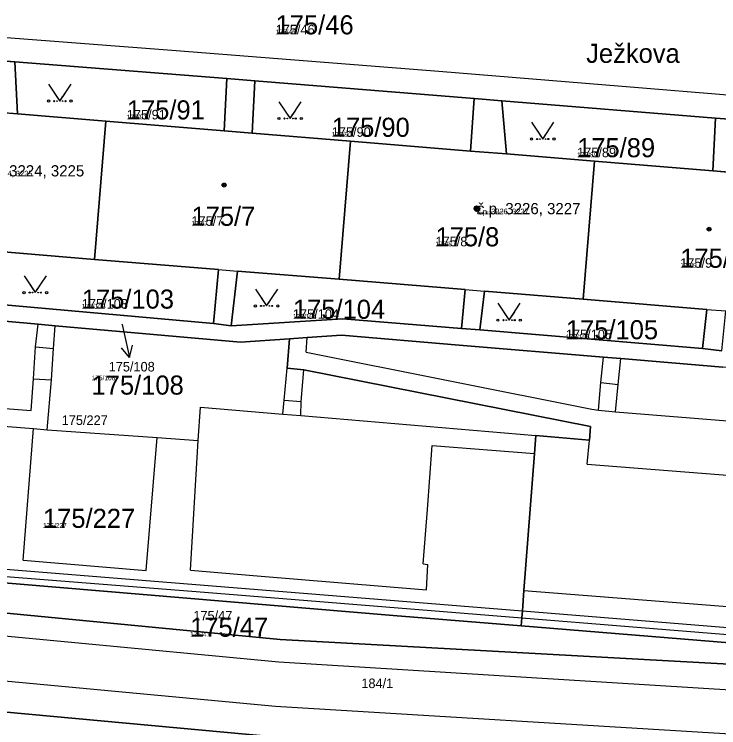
# Model space of a CAD drawing. Extents: x -759873 to -758487, y -975024 to -973516.
# Drawn here: x -759605.8 to -759543, y -974770.4 to -974706.8 of the extents above; entities that cross this region are included whole.
import ezdxf

# ---------------------------------------------------------------- set-up
doc = ezdxf.new("R2010")
doc.units = 0
for name, color, linetype in [('KAT_02_hranice parcel', 7, 'Continuous'), ('KAT_03_1000_st čísla parcelní', 7, 'Continuous'), ('KAT_03_1000_čísla parcelní', 7, 'Continuous'), ('KAT_03_1000_čísla popisná', 7, 'Continuous'), ('KAT_03_250_st čísla parcelní', 7, 'Continuous'), ('KAT_03_250_čísla parcelní', 7, 'Continuous'), ('KAT_03_250_čísla popisná', 7, 'Continuous'), ('KAT_03_500_st čísla parcelní', 7, 'Continuous'), ('KAT_03_500_čísla parcelní', 7, 'Continuous'), ('KAT_03_500_čísla popisná', 7, 'Continuous'), ('KAT_04_vnitřní kresba', 7, 'Continuous'), ('KAT_05_1000_značky kultur', 7, 'Continuous'), ('KAT_05_250_značky kultur', 7, 'Continuous'), ('KAT_05_500_značky kultur', 7, 'Continuous'), ('KAT_07_1000_značky budov', 7, 'Continuous'), ('KAT_07_250_značky budov', 7, 'Continuous'), ('KAT_07_500_značky budov', 7, 'Continuous'), ('KAT_12_pomocná šipka', 7, 'Continuous'), ('KAT_13_popis', 7, 'Continuous'), ('KAT_14_plocha_budovy', 7, 'Continuous'), ('KAT_14_plocha_pozemek', 7, 'Continuous')]:
    doc.layers.add(name, color=color, linetype=linetype)

msp = doc.modelspace()

# ---------------------------------------------------------------- linework, layer by layer
at = {"layer": 'KAT_02_hranice parcel'}
for p, q in [((-759605.74, -974711.03), (-759608.29, -974710.84)), ((-759605.74, -974711.03), (-759586.84, -974712.52)), ((-759584.35, -974712.72), (-759586.84, -974712.52)), ((-759584.35, -974712.72), (-759564.79, -974714.3)), ((-759562.33, -974714.49), (-759564.79, -974714.3)), ((-759562.33, -974714.49), (-759543.3, -974716.04)), ((-759540.86, -974716.24), (-759543.3, -974716.04)), ((-759598.63, -974728.63), (-759597.63, -974716.32)), ((-759576.84, -974730.41), (-759575.83, -974718.1)), ((-759555.1, -974732.19), (-759554.09, -974719.88)), ((-759607.69, -974732.58), (-759588.03, -974734.34)), ((-759588.03, -974734.34), (-759586.45, -974734.54)), ((-759565.94, -974734.78), (-759564.29, -974734.9)), ((-759564.29, -974734.9), (-759544.46, -974736.56)), ((-759544.46, -974736.56), (-759542.72, -974736.79))]:
    msp.add_line(p, q, dxfattribs=at)
for points in [[(-759597.63, -974716.32), (-759605.49, -974715.67), (-759605.74, -974711.03)], [(-759586.84, -974712.52), (-759587.06, -974717.18), (-759597.63, -974716.32)], [(-759575.83, -974718.1), (-759584.58, -974717.38), (-759584.35, -974712.72)], [(-759564.79, -974714.3), (-759565.13, -974718.98), (-759575.83, -974718.1)], [(-759554.09, -974719.88), (-759561.93, -974719.24), (-759562.33, -974714.49)], [(-759543.3, -974716.04), (-759543.55, -974720.74), (-759554.09, -974719.88)], [(-759607.69, -974732.58), (-759607.44, -974727.9), (-759598.63, -974728.63)], [(-759598.63, -974728.63), (-759587.58, -974729.53), (-759588.03, -974734.34)], [(-759586.45, -974734.54), (-759585.9, -974729.67), (-759576.84, -974730.41)], [(-759576.84, -974730.41), (-759565.6, -974731.33), (-759565.94, -974734.78)], [(-759647.22, -974730.88), (-759631.63, -974732.18), (-759609.62, -974733.88), (-759603.65, -974734.41), (-759602.12, -974734.54), (-759585.63, -974736), (-759581.26, -974735.71)], [(-759564.29, -974734.9), (-759563.89, -974731.47), (-759555.1, -974732.19)], [(-759555.1, -974732.19), (-759544.08, -974733.09), (-759544.46, -974736.56)], [(-759586.45, -974734.54), (-759576.49, -974733.94), (-759565.94, -974734.78)], [(-759560.6, -974761.29), (-759560.55, -974760.58), (-759560.5, -974759.95), (-759560.36, -974758.15), (-759559.43, -974745.94), (-759559.31, -974744.32), (-759554.53, -974744.73), (-759554.44, -974743.54), (-759579.98, -974738.48), (-759581.47, -974738.34), (-759581.26, -974735.71)], [(-759581.26, -974735.71), (-759579.69, -974735.6), (-759576.63, -974735.4), (-759566.14, -974736.28), (-759553.29, -974737.35), (-759551.74, -974737.48), (-759542.64, -974738.23), (-759533.6, -974737.86), (-759522.38, -974738.72), (-759521.14, -974738.82), (-759519.61, -974738.95), (-759501.03, -974740.46), (-759491.12, -974741.19), (-759489.77, -974741.29), (-759476.55, -974756.74), (-759476.86, -974759.46)], [(-759717.74, -974748.2), (-759711.27, -974749.14), (-759692.25, -974751.9), (-759582.09, -974762.5), (-759499.92, -974767.02), (-759477.49, -974765.76)], [(-759560.6, -974761.29), (-759572.03, -974760.36), (-759609.16, -974757.26), (-759640.37, -974754.73), (-759646.11, -974754.26), (-759649.25, -974754), (-759649.17, -974753.04)], [(-759476.86, -974759.46), (-759487.41, -974763.2), (-759493, -974765.18), (-759493.62, -974765.4), (-759505, -974765.42), (-759509.25, -974765.19), (-759519.89, -974764.5), (-759540.59, -974762.91), (-759560.6, -974761.29)], [(-759493.33, -974775.87), (-759498.32, -974775.83), (-759582.59, -974771.17), (-759622.27, -974767.52)]]:
    msp.add_lwpolyline(points, dxfattribs=at)
at = {"layer": 'KAT_03_1000_čísla popisná'}
msp.add_circle((-759564.55, -974724.11), 0.25, dxfattribs=at)
at = {"layer": 'KAT_03_250_čísla popisná'}
msp.add_circle((-759564.55, -974724.11), 0.0625, dxfattribs=at)
at = {"layer": 'KAT_03_500_čísla popisná'}
msp.add_circle((-759564.55, -974724.11), 0.125, dxfattribs=at)
at = {"layer": 'KAT_04_vnitřní kresba'}
for p, q in [((-759610.08, -974708.57), (-759591.35, -974710.02)), ((-759591.35, -974710.02), (-759567.96, -974711.85)), ((-759567.96, -974711.85), (-759551.6, -974713.2)), ((-759551.6, -974713.2), (-759535.51, -974714.52)), ((-759608.7, -974715.41), (-759605.49, -974715.67)), ((-759587.06, -974717.18), (-759584.58, -974717.38)), ((-759565.13, -974718.98), (-759561.93, -974719.24)), ((-759543.55, -974720.74), (-759541.08, -974720.95)), ((-759587.58, -974729.53), (-759585.9, -974729.67)), ((-759565.6, -974731.33), (-759563.89, -974731.47)), ((-759544.08, -974733.09), (-759542.39, -974733.23)), ((-759603.87, -974736.43), (-759603.65, -974734.41)), ((-759602.29, -974736.57), (-759602.12, -974734.54)), ((-759579.77, -974736.89), (-759579.69, -974735.6)), ((-759604.05, -974739.28), (-759603.87, -974736.43)), ((-759603.87, -974736.43), (-759602.29, -974736.57)), ((-759602.46, -974739.37), (-759602.29, -974736.57)), ((-759579.77, -974736.89), (-759554.32, -974741.98)), ((-759553.52, -974739.61), (-759553.29, -974737.35)), ((-759551.97, -974739.79), (-759551.74, -974737.48)), ((-759581.72, -974741.19), (-759581.47, -974738.34)), ((-759580.22, -974741.31), (-759579.98, -974738.48)), ((-759604.26, -974742.11), (-759604.05, -974739.28)), ((-759604.05, -974739.28), (-759602.46, -974739.37)), ((-759602.83, -974743.81), (-759602.46, -974739.37)), ((-759553.73, -974742.08), (-759553.52, -974739.61)), ((-759553.52, -974739.61), (-759551.97, -974739.79)), ((-759552.21, -974742.23), (-759551.97, -974739.79)), ((-759581.84, -974742.42), (-759581.72, -974741.19)), ((-759581.72, -974741.19), (-759580.22, -974741.31)), ((-759580.24, -974742.55), (-759580.22, -974741.31)), ((-759606.6, -974741.93), (-759604.26, -974742.11)), ((-759589.39, -974744.77), (-759589.18, -974741.81)), ((-759589.18, -974741.81), (-759581.84, -974742.42)), ((-759554.32, -974741.98), (-759553.73, -974742.08)), ((-759553.73, -974742.08), (-759552.21, -974742.23)), ((-759552.21, -974742.23), (-759521.62, -974744.68)), ((-759581.84, -974742.42), (-759580.24, -974742.55)), ((-759580.24, -974742.55), (-759559.31, -974744.32)), ((-759606.74, -974743.5), (-759604.06, -974743.71)), ((-759604.97, -974755.44), (-759604.06, -974743.71)), ((-759604.06, -974743.71), (-759602.83, -974743.81)), ((-759602.83, -974743.81), (-759593.05, -974744.52)), ((-759594.01, -974756.35), (-759593.05, -974744.52)), ((-759593.05, -974744.52), (-759589.39, -974744.77)), ((-759590.08, -974756.34), (-759589.39, -974744.77)), ((-759554.72, -974746.88), (-759554.53, -974744.73)), ((-759568.97, -974750.93), (-759568.54, -974745.21)), ((-759568.54, -974745.21), (-759559.43, -974745.94)), ((-759554.72, -974746.88), (-759495.5, -974751.55)), ((-759569.34, -974755.75), (-759568.97, -974750.93)), ((-759692.41, -974754), (-759582.2, -974764.5)), ((-759624.72, -974755.47), (-759588.82, -974758.29)), ((-759604.97, -974755.44), (-759594.01, -974756.35)), ((-759607.85, -974756.12), (-759560.5, -974759.95)), ((-759569.34, -974755.75), (-759568.93, -974755.82)), ((-759569.06, -974758.08), (-759568.93, -974755.82)), ((-759590.08, -974756.34), (-759584.14, -974756.83)), ((-759584.14, -974756.83), (-759569.06, -974758.08)), ((-759692.8, -974758.18), (-759582.51, -974768.44)), ((-759560.36, -974758.15), (-759496.41, -974763.18)), ((-759588.82, -974758.29), (-759560.55, -974760.58)), ((-759560.5, -974759.95), (-759541.05, -974761.52)), ((-759560.55, -974760.58), (-759540.53, -974762.2)), ((-759582.2, -974764.5), (-759498.6, -974769.65)), ((-759582.51, -974768.44), (-759498.27, -974773.58))]:
    msp.add_line(p, q, dxfattribs=at)
at = {"layer": 'KAT_05_1000_značky kultur'}
for points in [[(-759602.72, -974713.029), (-759601.72, -974714.53), (-759600.72, -974713.029)], [(-759582.2, -974714.579), (-759581.2, -974716.08), (-759580.2, -974714.579)], [(-759559.69, -974716.409), (-759558.69, -974717.91), (-759557.69, -974716.409)], [(-759604.9, -974730.089), (-759603.9, -974731.59), (-759602.9, -974730.089)], [(-759584.29, -974731.279), (-759583.29, -974732.78), (-759582.29, -974731.279)], [(-759562.69, -974732.549), (-759561.69, -974734.05), (-759560.69, -974732.549)]]:
    msp.add_lwpolyline(points, dxfattribs=at)
for centre in [(-759602.72, -974714.529), (-759600.72, -974714.529), (-759582.2, -974716.079), (-759580.2, -974716.079), (-759559.69, -974717.909), (-759557.69, -974717.909), (-759604.9, -974731.589), (-759602.9, -974731.589), (-759584.29, -974732.779), (-759582.29, -974732.779), (-759562.69, -974734.049), (-759560.69, -974734.049)]:
    msp.add_circle(centre, 0.1, dxfattribs=at)
at = {"layer": 'KAT_05_250_značky kultur'}
for points in [[(-759601.97, -974714.155), (-759601.72, -974714.53), (-759601.47, -974714.155)], [(-759581.45, -974715.705), (-759581.2, -974716.08), (-759580.95, -974715.705)], [(-759558.94, -974717.535), (-759558.69, -974717.91), (-759558.44, -974717.535)], [(-759604.15, -974731.215), (-759603.9, -974731.59), (-759603.65, -974731.215)], [(-759583.54, -974732.405), (-759583.29, -974732.78), (-759583.04, -974732.405)], [(-759561.94, -974733.675), (-759561.69, -974734.05), (-759561.44, -974733.675)]]:
    msp.add_lwpolyline(points, dxfattribs=at)
for centre in [(-759601.97, -974714.53), (-759601.47, -974714.53), (-759581.45, -974716.08), (-759580.95, -974716.08), (-759558.94, -974717.91), (-759558.44, -974717.91), (-759604.15, -974731.59), (-759603.65, -974731.59), (-759583.54, -974732.78), (-759583.04, -974732.78), (-759561.94, -974734.05), (-759561.44, -974734.05)]:
    msp.add_circle(centre, 0.025, dxfattribs=at)
at = {"layer": 'KAT_05_500_značky kultur'}
for points in [[(-759602.22, -974713.78), (-759601.72, -974714.53), (-759601.22, -974713.78)], [(-759581.7, -974715.329), (-759581.2, -974716.08), (-759580.7, -974715.329)], [(-759559.19, -974717.16), (-759558.69, -974717.91), (-759558.19, -974717.16)], [(-759604.4, -974730.84), (-759603.9, -974731.59), (-759603.4, -974730.84)], [(-759583.79, -974732.03), (-759583.29, -974732.78), (-759582.79, -974732.03)], [(-759562.19, -974733.299), (-759561.69, -974734.05), (-759561.19, -974733.299)]]:
    msp.add_lwpolyline(points, dxfattribs=at)
for centre in [(-759602.22, -974714.53), (-759601.22, -974714.53), (-759581.7, -974716.08), (-759580.7, -974716.08), (-759559.19, -974717.91), (-759558.19, -974717.91), (-759604.4, -974731.59), (-759603.4, -974731.59), (-759583.79, -974732.78), (-759582.79, -974732.78), (-759562.19, -974734.05), (-759561.19, -974734.05)]:
    msp.add_circle(centre, 0.05, dxfattribs=at)
at = {"layer": 'KAT_07_1000_značky budov'}
for centre in [(-759587.077, -974722.009), (-759564.557, -974724.109), (-759543.867, -974725.939)]:
    msp.add_circle(centre, 0.175, dxfattribs=at)
at = {"layer": 'KAT_07_250_značky budov'}
for centre in [(-759587.072, -974722.01), (-759564.552, -974724.11), (-759543.862, -974725.94)]:
    msp.add_circle(centre, 0.0437, dxfattribs=at)
at = {"layer": 'KAT_07_500_značky budov'}
for centre in [(-759587.073, -974722.01), (-759564.553, -974724.11), (-759543.863, -974725.94)]:
    msp.add_circle(centre, 0.0875, dxfattribs=at)
at = {"layer": 'KAT_12_pomocná šipka'}
for p, q in [((-759596.18, -974734.41), (-759596.17, -974734.45)), ((-759596.17, -974734.45), (-759595.495, -974737.374)), ((-759595.495, -974737.374), (-759596.208, -974736.511)), ((-759595.495, -974737.374), (-759595.232, -974736.286))]:
    msp.add_line(p, q, dxfattribs=at)
at = {"layer": 'KAT_14_plocha_budovy'}
for points in [[(-759620.43, -974726.84), (-759609.16, -974727.76), (-759607.44, -974727.9), (-759598.63, -974728.63), (-759587.58, -974729.53), (-759585.9, -974729.67), (-759576.84, -974730.41), (-759575.83, -974718.1), (-759584.58, -974717.38), (-759587.06, -974717.18), (-759597.63, -974716.32), (-759605.49, -974715.67), (-759608.7, -974715.41), (-759619.43, -974714.53), (-759619.53, -974715.73)], [(-759576.84, -974730.41), (-759565.6, -974731.33), (-759563.89, -974731.47), (-759555.1, -974732.19), (-759544.08, -974733.09), (-759542.39, -974733.23), (-759533.36, -974733.97), (-759533.26, -974732.77), (-759532.35, -974721.66), (-759541.08, -974720.95), (-759543.55, -974720.74), (-759554.09, -974719.88), (-759561.93, -974719.24), (-759565.13, -974718.98), (-759575.83, -974718.1)]]:
    msp.add_lwpolyline(points, close=True, dxfattribs=at)
at = {"layer": 'KAT_14_plocha_pozemek'}
for points in [[(-759609.16, -974727.76), (-759609.42, -974732.4), (-759607.69, -974732.58), (-759607.44, -974727.9), (-759598.63, -974728.63), (-759597.63, -974716.32), (-759605.49, -974715.67), (-759605.74, -974711.03), (-759608.29, -974710.84), (-759608.7, -974715.41), (-759619.43, -974714.53), (-759619.53, -974715.73), (-759620.43, -974726.84)], [(-759605.74, -974711.03), (-759605.49, -974715.67), (-759597.63, -974716.32), (-759587.06, -974717.18), (-759586.84, -974712.52)], [(-759587.58, -974729.53), (-759588.03, -974734.34), (-759586.45, -974734.54), (-759585.9, -974729.67), (-759576.84, -974730.41), (-759575.83, -974718.1), (-759584.58, -974717.38), (-759584.35, -974712.72), (-759586.84, -974712.52), (-759587.06, -974717.18), (-759597.63, -974716.32), (-759598.63, -974728.63)], [(-759584.35, -974712.72), (-759584.58, -974717.38), (-759575.83, -974718.1), (-759565.13, -974718.98), (-759564.79, -974714.3)], [(-759554.09, -974719.88), (-759561.93, -974719.24), (-759562.33, -974714.49), (-759564.79, -974714.3), (-759565.13, -974718.98), (-759575.83, -974718.1), (-759576.84, -974730.41), (-759565.6, -974731.33), (-759565.94, -974734.78), (-759564.29, -974734.9), (-759563.89, -974731.47), (-759555.1, -974732.19)], [(-759562.33, -974714.49), (-759561.93, -974719.24), (-759554.09, -974719.88), (-759543.55, -974720.74), (-759543.3, -974716.04)], [(-759540.86, -974716.24), (-759543.3, -974716.04), (-759543.55, -974720.74), (-759554.09, -974719.88), (-759555.1, -974732.19), (-759544.08, -974733.09), (-759544.46, -974736.56), (-759542.72, -974736.79), (-759542.39, -974733.23), (-759533.36, -974733.97), (-759533.26, -974732.77), (-759532.35, -974721.66), (-759541.08, -974720.95)], [(-759588.03, -974734.34), (-759587.58, -974729.53), (-759598.63, -974728.63), (-759607.44, -974727.9), (-759607.69, -974732.58)], [(-759565.94, -974734.78), (-759565.6, -974731.33), (-759576.84, -974730.41), (-759585.9, -974729.67), (-759586.45, -974734.54), (-759576.49, -974733.94)], [(-759560.55, -974760.58), (-759560.5, -974759.95), (-759560.36, -974758.15), (-759559.43, -974745.94), (-759559.31, -974744.32), (-759554.53, -974744.73), (-759554.44, -974743.54), (-759579.98, -974738.48), (-759581.47, -974738.34), (-759581.26, -974735.71), (-759585.63, -974736), (-759602.12, -974734.54), (-759603.65, -974734.41), (-759609.62, -974733.88), (-759631.63, -974732.18), (-759647.22, -974730.88), (-759647.39, -974732.84), (-759649.17, -974753.04), (-759649.25, -974754), (-759646.11, -974754.26), (-759640.37, -974754.73), (-759609.16, -974757.26), (-759572.03, -974760.36), (-759560.6, -974761.29)], [(-759544.46, -974736.56), (-759544.08, -974733.09), (-759555.1, -974732.19), (-759563.89, -974731.47), (-759564.29, -974734.9)], [(-759493.33, -974775.87), (-759498.32, -974775.83), (-759582.59, -974771.17), (-759622.27, -974767.52), (-759617.87, -974768.52), (-759619.06, -974771.36), (-759617.11, -974774.92), (-759613.56, -974776.84), (-759610.35, -974777.27), (-759609.95, -974772.38), (-759572.8, -974775.33), (-759541.75, -974777.79), (-759500.3, -974781.07), (-759500.61, -974785.93), (-759495.44, -974785.77), (-759491.14, -974783.19), (-759489.31, -974781.1), (-759489.41, -974779.52), (-759492.24, -974776.63)]]:
    msp.add_lwpolyline(points, close=True, dxfattribs=at)
for points in [[(-759608.29, -974710.84), (-759605.74, -974711.03), (-759586.84, -974712.52), (-759584.35, -974712.72), (-759564.79, -974714.3), (-759562.33, -974714.49), (-759543.3, -974716.04), (-759540.86, -974716.24), (-759521.3, -974717.76), (-759518.83, -974717.97), (-759499.69, -974719.44), (-759497.33, -974719.66), (-759472.52, -974721.69), (-759471.04, -974721.83), (-759456.84, -974723.48), (-759441.08, -974726.05)], [(-759542.72, -974736.79), (-759544.46, -974736.56), (-759564.29, -974734.9), (-759565.94, -974734.78), (-759576.49, -974733.94), (-759586.45, -974734.54), (-759588.03, -974734.34), (-759607.69, -974732.58)], [(-759609.62, -974733.88), (-759603.65, -974734.41), (-759602.12, -974734.54), (-759585.63, -974736), (-759581.26, -974735.71), (-759579.69, -974735.6), (-759576.63, -974735.4), (-759566.14, -974736.28), (-759553.29, -974737.35), (-759551.74, -974737.48), (-759542.64, -974738.23)], [(-759542.64, -974738.23), (-759551.74, -974737.48), (-759553.29, -974737.35), (-759566.14, -974736.28), (-759576.63, -974735.4), (-759579.69, -974735.6), (-759581.26, -974735.71), (-759581.47, -974738.34), (-759579.98, -974738.48), (-759554.44, -974743.54), (-759554.53, -974744.73), (-759559.31, -974744.32), (-759559.43, -974745.94), (-759560.36, -974758.15), (-759560.5, -974759.95), (-759560.55, -974760.58), (-759560.6, -974761.29), (-759540.59, -974762.91)], [(-759440.41, -974758.08), (-759470.53, -974765.37), (-759475.45, -974765.65), (-759475.72, -974768.33), (-759477.76, -974768.37), (-759477.49, -974765.76), (-759499.92, -974767.02), (-759582.09, -974762.5), (-759692.25, -974751.9)], [(-759692.25, -974751.9), (-759582.09, -974762.5), (-759499.92, -974767.02), (-759477.49, -974765.76), (-759476.86, -974759.46), (-759487.41, -974763.2), (-759493, -974765.18), (-759493.62, -974765.4), (-759505, -974765.42), (-759509.25, -974765.19), (-759519.89, -974764.5), (-759540.59, -974762.91), (-759560.6, -974761.29), (-759572.03, -974760.36), (-759609.16, -974757.26)], [(-759622.27, -974767.52), (-759582.59, -974771.17)]]:
    msp.add_lwpolyline(points, dxfattribs=at)

# ---------------------------------------------------------------- texts
at = {"layer": 'KAT_03_1000_st čísla parcelní'}
for s, p in [('175/7', (-759589.99, -974725.64)), ('175/8', (-759568.25, -974727.47)), ('175/9', (-759546.44, -974729.38))]:
    msp.add_text(s, height=1.7, dxfattribs=at).set_placement(p)
at = {"layer": 'KAT_03_1000_čísla parcelní'}
for s, p in [('175/46', (-759582.49, -974708.58)), ('175/91', (-759595.75, -974716.16)), ('175/90', (-759577.49, -974717.71)), ('175/89', (-759555.63, -974719.53)), ('175/103', (-759599.76, -974733.02)), ('175/104', (-759580.95, -974733.929)), ('175/105', (-759556.63, -974735.75)), ('175/108', (-759598.89, -974740.683)), ('175/227', (-759603.22, -974752.559)), ('175/47', (-759590.11, -974762.26))]:
    msp.add_text(s, height=1.7, dxfattribs=at).set_placement(p)
at = {"layer": 'KAT_03_1000_čísla popisná'}
for s, p in [('č.p. 3224, 3225', (-759608.76, -974721.24)), ('č.p. 3226, 3227', (-759564.55, -974724.61))]:
    msp.add_text(s, height=1, dxfattribs=at).set_placement(p)
at = {"layer": 'KAT_03_250_st čísla parcelní'}
for s, p in [('175/7', (-759589.99, -974725.64)), ('175/8', (-759568.25, -974727.47)), ('175/9', (-759546.44, -974729.38))]:
    msp.add_text(s, height=0.425, dxfattribs=at).set_placement(p)
at = {"layer": 'KAT_03_250_čísla parcelní'}
for s, p in [('175/46', (-759582.49, -974708.58)), ('175/91', (-759595.75, -974716.16)), ('175/90', (-759577.49, -974717.71)), ('175/89', (-759555.63, -974719.53)), ('175/103', (-759599.76, -974733.02)), ('175/104', (-759580.95, -974733.929)), ('175/105', (-759556.63, -974735.75)), ('175/108', (-759598.89, -974739.408)), ('175/227', (-759603.22, -974752.559)), ('175/47', (-759590.11, -974762.26))]:
    msp.add_text(s, height=0.425, dxfattribs=at).set_placement(p)
at = {"layer": 'KAT_03_250_čísla popisná'}
msp.add_text('č.p. 3226, 3227', height=0.25, dxfattribs=at).set_placement((-759564.55, -974724.61))
at = {"layer": 'KAT_03_500_st čísla parcelní'}
for s, p in [('175/7', (-759589.99, -974725.64)), ('175/8', (-759568.25, -974727.47)), ('175/9', (-759546.44, -974729.38))]:
    msp.add_text(s, height=0.85, dxfattribs=at).set_placement(p)
at = {"layer": 'KAT_03_500_čísla parcelní'}
for s, p in [('175/46', (-759582.49, -974708.58)), ('175/91', (-759595.75, -974716.16)), ('175/90', (-759577.49, -974717.71)), ('175/89', (-759555.63, -974719.53)), ('175/103', (-759599.76, -974733.02)), ('175/104', (-759580.95, -974733.929)), ('175/105', (-759556.63, -974735.75)), ('175/108', (-759597.368, -974738.621)), ('175/227', (-759601.551, -974743.387)), ('175/47', (-759589.822, -974760.812)), ('184/1', (-759574.855, -974766.837))]:
    msp.add_text(s, height=0.85, dxfattribs=at).set_placement(p)
at = {"layer": 'KAT_03_500_čísla popisná'}
for s, p in [('č.p. 3224, 3225', (-759608.76, -974721.24)), ('č.p. 3226, 3227', (-759564.55, -974724.61))]:
    msp.add_text(s, height=0.5, dxfattribs=at).set_placement(p)
at = {"layer": 'KAT_13_popis'}
msp.add_text('Ježkova', height=1.7, dxfattribs=at).set_placement((-759554.82, -974711.12))

doc.saveas('drawing.dxf')
